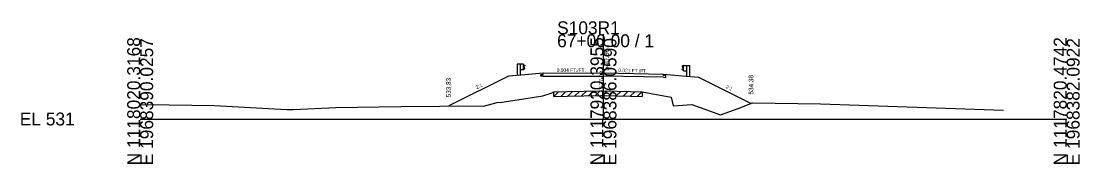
# Model space of a CAD drawing. Extents: x -26 to 203, y -10 to 12018.
# Drawn here: x -25.7 to 202.8, y 7490.3 to 7521.2 of the extents above; entities that cross this region are included whole.
import ezdxf

# ---------------------------------------------------------------- set-up
doc = ezdxf.new("R2010")
doc.units = 0
for name, color, linetype in [('Level 10', 7, 'Continuous'), ('Level 11', 7, 'Continuous'), ('Level 12', 7, 'Continuous'), ('Level 24', 7, 'Continuous'), ('Level 32', 7, 'Continuous'), ('Level 33', 7, 'Continuous'), ('Level 59', 7, 'Continuous'), ('Level 6', 7, 'Continuous'), ('Level 60', 7, 'Continuous'), ('Level 61', 7, 'Continuous'), ('Level 63', 7, 'Continuous'), ('Level 7', 7, 'Continuous')]:
    doc.layers.add(name, color=color, linetype=linetype)

msp = doc.modelspace()

# ---------------------------------------------------------------- linework, layer by layer
at = {"layer": 'Level 11'}
for p, q in [((86.5, 7509.59), (87, 7509.59)), ((86.5, 7509.23), (86.5, 7509.59)), ((87, 7509.59), (87, 7509.91)), ((113, 7509.37), (113, 7509.68)), ((87, 7509.23), (86.5, 7509.23)), ((113.5, 7509.36), (113, 7509.37)), ((113, 7509.01), (113.5, 7509)), ((113.5, 7509), (113.5, 7509.36))]:
    msp.add_line(p, q, dxfattribs=at)
at = {"layer": 'Level 12'}
for p in [(87, 7509.23), (113, 7509.01)]:
    msp.add_line(p, (100, 7509.28), dxfattribs=at)
at = {"layer": 'Level 24'}
for p, q in [((82.06, 7511.82), (81.4, 7511.82)), ((81.4, 7511.82), (81.4, 7509.44)), ((82.73, 7511.82), (82.06, 7511.82)), ((82.06, 7511.82), (82.06, 7509.5)), ((82.73, 7510.66), (82.06, 7510.66)), ((82.73, 7510.66), (82.73, 7511.82)), ((82.73, 7511.75), (83, 7511.55)), ((83, 7511.5), (82.73, 7511.3)), ((83, 7510.98), (82.73, 7511.18)), ((82.73, 7510.73), (83, 7510.93)), ((83, 7511.55), (83, 7511.5)), ((83, 7510.93), (83, 7510.98)), ((117.27, 7511.53), (117, 7511.33)), ((117, 7511.33), (117, 7511.28)), ((117, 7511.28), (117.27, 7511.08)), ((117, 7510.76), (117.27, 7510.96)), ((117, 7510.71), (117, 7510.76)), ((117.27, 7510.51), (117, 7510.71)), ((117.27, 7510.43), (117.27, 7511.6)), ((117.27, 7511.6), (117.94, 7511.6)), ((117.27, 7510.43), (117.94, 7510.43)), ((117.94, 7511.6), (117.94, 7509.27)), ((117.94, 7511.6), (118.6, 7511.6)), ((118.6, 7511.6), (118.6, 7509.22))]:
    msp.add_line(p, q, dxfattribs=at)
at = {"layer": 'Level 59'}
for p, q in [((87, 7509.91), (100, 7509.96)), ((100, 7509.96), (113, 7509.68))]:
    msp.add_line(p, q, dxfattribs=at)
at = {"layer": 'Level 6'}
for p, q in [((87, 7509.91), (83, 7509.57)), ((113, 7509.68), (117, 7509.35)), ((83, 7509.57), (79.5, 7509.28)), ((117, 7509.35), (120.5, 7509.06))]:
    msp.add_line(p, q, dxfattribs=at)
at = {"layer": 'Level 60'}
for p, q in [((81.36, 7504.18), (86.89, 7505.02)), ((86.89, 7505.02), (88.7, 7505.58)), ((88.7, 7505.58), (89.28, 7505.84)), ((89.28, 7505.84), (92.18, 7505.91)), ((92.18, 7505.91), (99.41, 7506.1)), ((99.41, 7506.1), (100, 7506.09)), ((100, 7506.09), (105.85, 7505.91)), ((105.85, 7505.91), (108.38, 7505.84)), ((108.38, 7505.84), (110.34, 7505.51)), ((110.34, 7505.51), (114.59, 7504.75)), ((0, 7503.16), (6.29, 7503.05)), ((6.29, 7503.05), (16.05, 7502.92)), ((16.05, 7502.92), (30.29, 7502.1)), ((56.24, 7502.69), (64.69, 7502.8)), ((64.69, 7502.8), (68.63, 7502.86)), ((68.63, 7502.86), (74.14, 7502.79)), ((74.14, 7502.79), (77.04, 7503.59)), ((77.04, 7503.59), (78.09, 7503.65)), ((78.09, 7503.65), (81.36, 7504.18)), ((114.59, 7504.75), (115.08, 7502.87)), ((115.08, 7502.87), (119.1, 7503.12)), ((119.1, 7503.12), (125.26, 7500.88)), ((129.09, 7502.24), (132.2, 7503.52)), ((132.2, 7503.52), (146.86, 7503.27)), ((146.86, 7503.27), (186.35, 7501.92)), ((30.29, 7502.1), (31.74, 7502.02)), ((31.74, 7502.02), (33.09, 7502.08)), ((33.09, 7502.08), (42.23, 7502.51)), ((42.23, 7502.51), (56.24, 7502.69)), ((125.26, 7500.88), (129.09, 7502.24))]:
    msp.add_line(p, q, dxfattribs=at)
at = {"layer": 'Level 61'}
for p, q in [((89.28, 7504.84), (90.31, 7505.86)), ((89.28, 7504.84), (89.28, 7505.84)), ((90.78, 7504.87), (91.81, 7505.9)), ((92.18, 7504.91), (99.41, 7505.1)), ((92.28, 7504.91), (93.31, 7505.94)), ((93.78, 7504.95), (94.81, 7505.98)), ((95.28, 7504.99), (96.31, 7506.02)), ((96.78, 7505.03), (97.81, 7506.06)), ((98.28, 7505.07), (99.31, 7506.1)), ((99.41, 7505.1), (100, 7505.09)), ((99.78, 7505.09), (100.76, 7506.06)), ((100, 7505.09), (105.85, 7504.91)), ((101.28, 7505.05), (102.26, 7506.02)), ((102.78, 7505), (103.76, 7505.97)), ((104.28, 7504.96), (105.26, 7505.93)), ((105.78, 7504.91), (106.76, 7505.88)), ((107.28, 7504.87), (108.26, 7505.84)), ((108.38, 7505.84), (108.38, 7504.84)), ((89.28, 7504.84), (92.18, 7504.91)), ((105.85, 7504.91), (108.38, 7504.84))]:
    msp.add_line(p, q, dxfattribs=at)
at = {"layer": 'Level 63'}
for p, q in [((100, 7500), (100, 7518.31)), ((0, 7500), (100, 7500)), ((100, 7500), (200, 7500))]:
    msp.add_line(p, q, dxfattribs=at)
at = {"layer": 'Level 7'}
for p, q in [((79.5, 7509.28), (66.6, 7502.83)), ((120.5, 7509.06), (131.86, 7503.38))]:
    msp.add_line(p, q, dxfattribs=at)

# ---------------------------------------------------------------- texts
at = {"layer": 'Level 10'}
msp.add_text(' 537.09', height=0.9, rotation=90, dxfattribs=at).set_placement((100, 7506.23))
at = {"layer": 'Level 32'}
for s, rotation, p in [('0.004 FT./FT.', 0.2126, (89.93, 7510.17)), ('0.021 FT./FT.', 358.8084, (103.22, 7510.14)), ('2:1', 26.5651, (72.65, 7506.43)), ('2:1', 333.4349, (126.34, 7506.71))]:
    msp.add_text(s, height=0.75, rotation=rotation, dxfattribs=at).set_placement(p)
at = {"layer": 'Level 33'}
for s, p in [('533.83', (67.05, 7504.68)), ('534.38', (132.36, 7505.28))]:
    msp.add_text(s, height=1, rotation=90, dxfattribs=at).set_placement(p)
at = {"layer": 'Level 59'}
msp.add_text(' 540.96', height=1.2, rotation=90, dxfattribs=at).set_placement((101.2, 7509.96))
at = {"layer": 'Level 63'}
for s, p in [('S103R1', (90, 7518.31)), ('67+00.00 / 1', (90, 7515.51)), ('EL 531', (-26, 7498.6))]:
    msp.add_text(s, height=2.8, dxfattribs=at).set_placement(p)
for s, p in [('N 1118020.3168', (0, 7490)), ('E 1968390.0257', (2.8, 7490)), ('N 1117920.3955', (100, 7490)), ('E 1968386.0590', (102.8, 7490)), ('N 1117820.4742', (200, 7490)), ('E 1968382.0922', (202.8, 7490))]:
    msp.add_text(s, height=2.8, rotation=90, dxfattribs=at).set_placement(p)

doc.saveas('drawing.dxf')
